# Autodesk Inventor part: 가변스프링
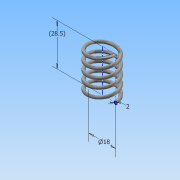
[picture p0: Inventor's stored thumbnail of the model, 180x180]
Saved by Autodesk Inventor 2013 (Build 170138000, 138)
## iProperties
Created: 2017-12
Part Number: 가변스프링
Material: 스테인리스강
Document SubType Name: Modeling
Designer: Administrator
Mass: 7.0703 g
Surface Area: 17.7408 cm^2
Volume: 0.875037 cm^3
Density: 8.08 g/cm^3
Author: Administrator
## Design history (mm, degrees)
sketch "스케치2"
  geometry: L1 (0, 0)-(-9, 0); L2 (-9, 0)-(-9, 28.5); L3 (-9, 28.5)-(0, 28.5); L4 (0, 28.5)-(0, 0); C1 r 1 at (-9, 0)
  constraints: 8 end point, 2 parallel, 1 centre point, 1 coincident, 1 horizontal, 1 perpendicular
  dimensions: "d0" = 28.49998 distance of L3.end L1.start (derived); "d1" = 18 diameter of L2 L4; "d2" = 2 diameter of C1
feature "코일1" sketch "스케치2" pitch "d3" = 10; turns "d5" = 5; dims "d4" = 28.49998 (= d0), "d6" = 0, angle "d7" = 90 deg, angle "d8" = 90 deg, "d9" = 0, "d10" = 0
node "작업 평면1"
feature "분할1"
feature "분할2"
node "솔리드1"
other parameters: "d11" = 0
